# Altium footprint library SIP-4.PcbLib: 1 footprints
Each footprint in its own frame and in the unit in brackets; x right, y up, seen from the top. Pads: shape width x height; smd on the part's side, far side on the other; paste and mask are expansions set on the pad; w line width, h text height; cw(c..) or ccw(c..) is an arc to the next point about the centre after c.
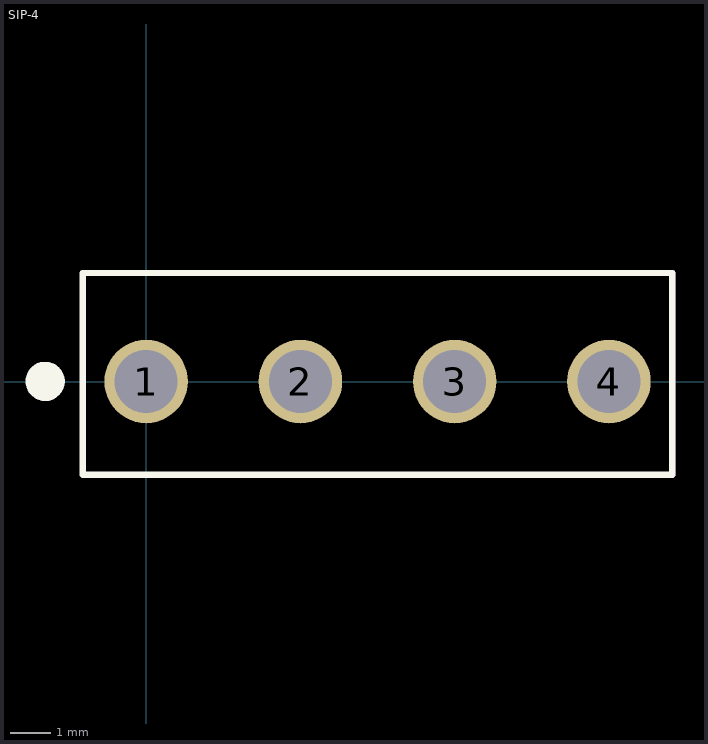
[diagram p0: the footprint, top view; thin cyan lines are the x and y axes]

## SIP-4 [mil]
pads (4):
  round 81 hole 61: 1(0,0) 2(149.61,0) 3(299.21,0) 4(448.82,0)
Top Overlay:
  circle w20: c-97.95,0.17 r9.04
  lines w6: -61.46,-90.36 510.13,-90.36 510.13,105.17 -61.46,105.17 -61.46,-90.36
Mechanical 15:
  lines w6: -61.33,-90.6 -61.33,105.24 510.13,105.24 510.13,-90.6 -61.33,-90.6
3D body "ALSRobot-BRIDGE KBPM.step": height 846.46, standoff -106.3, extent -63.84,-91.84 510.15,105.41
